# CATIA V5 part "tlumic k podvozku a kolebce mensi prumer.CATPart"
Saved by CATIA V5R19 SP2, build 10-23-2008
Part number: tlumic k podvozku a kolebce mensi prumer
Bounding box of the stored display mesh (mm): x -142.531 to 350, y -40 to 40, z -54.812 to 54.812
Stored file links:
  C:\Users\Martiin\Desktop\9.semestr\Projekt-diplomka\3D model\tlumic k podvozku a kolebce mensi prumer.CATPart
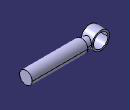
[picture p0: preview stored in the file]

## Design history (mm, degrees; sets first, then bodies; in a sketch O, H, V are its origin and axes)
Body1 (main body)
  Sketch1 on yz-plane, origin (0, 0, 0), H (0, 1, 0), V (0, 0, 1)
    circle A1 centre (0, 0) radius 40
    radius A1 = 40
  Pad1: profile Sketch1, direction (1, 0, 0), length 350
  Sketch2 on zx-plane, origin (0, 0, 0), H (-1, 0, 0), V (0, 0, 1)
    circle A1 centre (87.5305, 0) radius 45
    point P1 (87.5305, 0)
    circle A2 centre (87.5305, 0) radius 55
    radius A1 = 45
    radius A2 = 55
    coincidence: P1 H
  Pad2: profile Sketch2, direction (0, 1, 0), length 34, mirrored extent
  Sketch3 on start face of Pad1, origin (0, 0, 0), H (0, -1, 0), V (0, 0, 1)
    circle A1 centre (0, 0) radius 30
    radius A1 = 30
  Pad3: profile Sketch3, direction (-1, 0, 0), up to the existing solid (limit type 2)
